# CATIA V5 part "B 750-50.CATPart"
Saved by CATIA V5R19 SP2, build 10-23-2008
Part number: B 750-50
Bounding box of the stored display mesh (mm): x -22.494 to 22.494, y -22.494 to 22.494, z 0 to 185
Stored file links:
  C:\Users\Bora\Desktop\3D Katı model\B serisi\B 750\B 750-50.CATPart
  C:\Program Files\Dassault Systemes\B19\intel_a\reffiles\standard\MetricThickPitch.txt
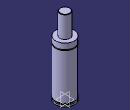
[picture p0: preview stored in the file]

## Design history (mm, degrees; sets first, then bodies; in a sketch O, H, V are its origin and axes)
Body1 (main body)
  Sketch1 on yz-plane, origin (0, 0, 0), H (0, 1, 0), V (0, 0, 1)
    point P3 (12, 184)
    point P5 (12, 184)
    point P7 (22.5, 119.5)
    point P8 (22.5, 117.5)
    point P12 (22.5, 117.5)
    point P13 (22.5, 119.5)
    line L1 (22.5, 0) -> (22.5, 4)
    line L2 (12, 184) -> (12, 133)
    arc A1 centre (11, 184) radius 1 from (12, 184) to (11, 185) ccw
    arc A2 centre (22.5, 118.5) radius 1 from (22.5, 119.5) to (22.5, 117.5) ccw
    line L3 (20, 7.5) -> (20, 4)
    line L4 (22.5, 7.5) -> (22.5, 117.5)
    line L5 (22.5, 119.5) -> (22.5, 133)
    line L6 (11, 185) -> (0, 185)
    point P15 (0, 185)
    line L7 (12, 133) -> (22.5, 133)
    line L8 (0, 0) -> (22.5, 0)
    line L9 (20, 7.5) -> (22.5, 7.5)
    line L10 (20, 4) -> (22.5, 4)
    coincidence: P15 V, P3 P5, P7 P13, P8 P12
    tangency: L6 A1
    horizontal: L7 H, L8 H, L9 H, L10 H
  Shaft1: profile Sketch1, axis Sketch1.V, angle 360
  Sketch2 on face of Shaft1 from Sketch1.L8, origin (0, 0, 0), H (1, 0, 0), V (0, -1, 0)
    point P1 (10, 0)
    distance P1 V = 10
  Hole1: placed by Sketch2, at (10, 0, 0) direction (0, 0, 1), diameter 6.647, depth 13, threaded "M8", thread diameter 8, thread depth 13, pitch 1.25
  CircPattern1: of Hole1, instances 2, angular step 180, axis from xy-plane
